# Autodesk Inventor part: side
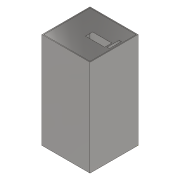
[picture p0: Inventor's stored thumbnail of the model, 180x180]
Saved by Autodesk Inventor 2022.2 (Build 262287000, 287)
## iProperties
Created: 2022-03
Part Number: side
Material: Stainless Steel
Document SubType Name: Modeling
Designer: OHIL G H
Density: 8 g/cm^3
Appearance: Semi-Polished
Author: OHIL G H
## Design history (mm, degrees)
sketch "Sketch1"
  geometry: L1 (0, 0)-(100, 0); L2 (100, 0)-(100, 200); L3 (100, 200)-(0, 200); L4 (0, 200)-(0, 0)
  constraints: 8 end point, 2 parallel, 1 horizontal, 1 perpendicular
  dimensions: "d0" = 100 distance of L3.end L2.end; "d1" = 200 distance of L2.end L1.end
extrude "Extrusion1" new body sketch "Sketch1" distance "d2" = 100; taper "d3" = 0 deg
sketch "Sketch2"
  geometry: L1 (2, 98)-(98, 98); L2 (98, 98)-(98, 2); L3 (98, 2)-(2, 2); L4 (2, 2)-(2, 98); L5 (0, 100)-(100, 100) reference; L6 (100, 0)-(100, 100) reference; L7 (0, 0)-(100, 0) reference; L8 (0, 0)-(0, 100) reference
  constraints: 8 end point, 2 parallel, 1 horizontal, 1 perpendicular
  dimensions: "d4" = 2 distance between parallel lines of L5 L1; "d5" = 2 distance between parallel lines of L6 L2; "d6" = 2 distance between parallel lines of L7 L3; "d7" = 2 distance between parallel lines of L8 L4
extrude "Extrusion2" cut sketch "Sketch2" distance "d8" = 199.8; taper "d9" = 0 deg
sketch "Sketch3"
  geometry: L1 (95.5, -30)-(90.5, -30); L2 (90.5, -30)-(90.5, -55); L3 (90.5, -55)-(95.5, -55); L4 (95.5, -55)-(95.5, -30); L5 (98, -98)-(98, -2) reference; L6 (100, 0)-(0, 0) reference; 1 further point
  constraints: 8 end point, 2 parallel, 1 horizontal, 1 midpoint, 1 perpendicular
  dimensions: "d10" = 5 distance of L3.end L2.end; "d11" = 25 distance of L2.end L1.end; "d12" = 2.5 distance between parallel lines of L5 L4; "d13" = 30 distance from line of L6 point (93, -30)
extrude "Extrusion3" cut sketch "Sketch3" extent not by distance; stored distance "d14" = 0; taper "d15" = 0 deg
sketch "Sketch4"
  geometry: L1 (48, -42.5)-(88, -42.5); L2 (88, -42.5)-(88, -57.5); L3 (88, -57.5)-(48, -57.5); L4 (48, -57.5)-(48, -42.5); L5 (100, 0)-(100, -100) reference; L6 (100, 0)-(0, 0) reference; 1 further point
  constraints: 8 end point, 2 parallel, 1 horizontal, 1 midpoint, 1 perpendicular
  dimensions: "d16" = 40 distance of L2.end L3.end; "d17" = 15 distance of L1.end L2.end; "d18" = 12 distance from line of L5 point (88, -50); "d19" = 42.5 distance between parallel lines of L1 L6
extrude "Extrusion4" cut sketch "Sketch4" extent not by distance; stored distance "d20" = 0; taper "d21" = 0 deg
sketch "Sketch5"
  geometry: 1 further point
sketch "Sketch6"
  geometry: L1 (0, 0)-(100, 0) reference; L2 (0, 200)-(0, 0) reference; C1 r 2.5 at (20, 20); C2 r 2.5 at (80, 20)
  constraints: 2 centre point
  dimensions: "d22" = 5 diameter of C1; "d23" = 5 diameter of C2; "d24" = 60 distance of C2.centre C1.centre; "d25" = 20 distance from line of L1 C1.centre; "d26" = 20 distance from line of L2 C1.centre; "d27" = 20 distance from line of L1 C2.centre
extrude "Extrusion5" cut sketch "Sketch6" distance "d28" = 10; taper "d29" = 0 deg
body "Solid1"
